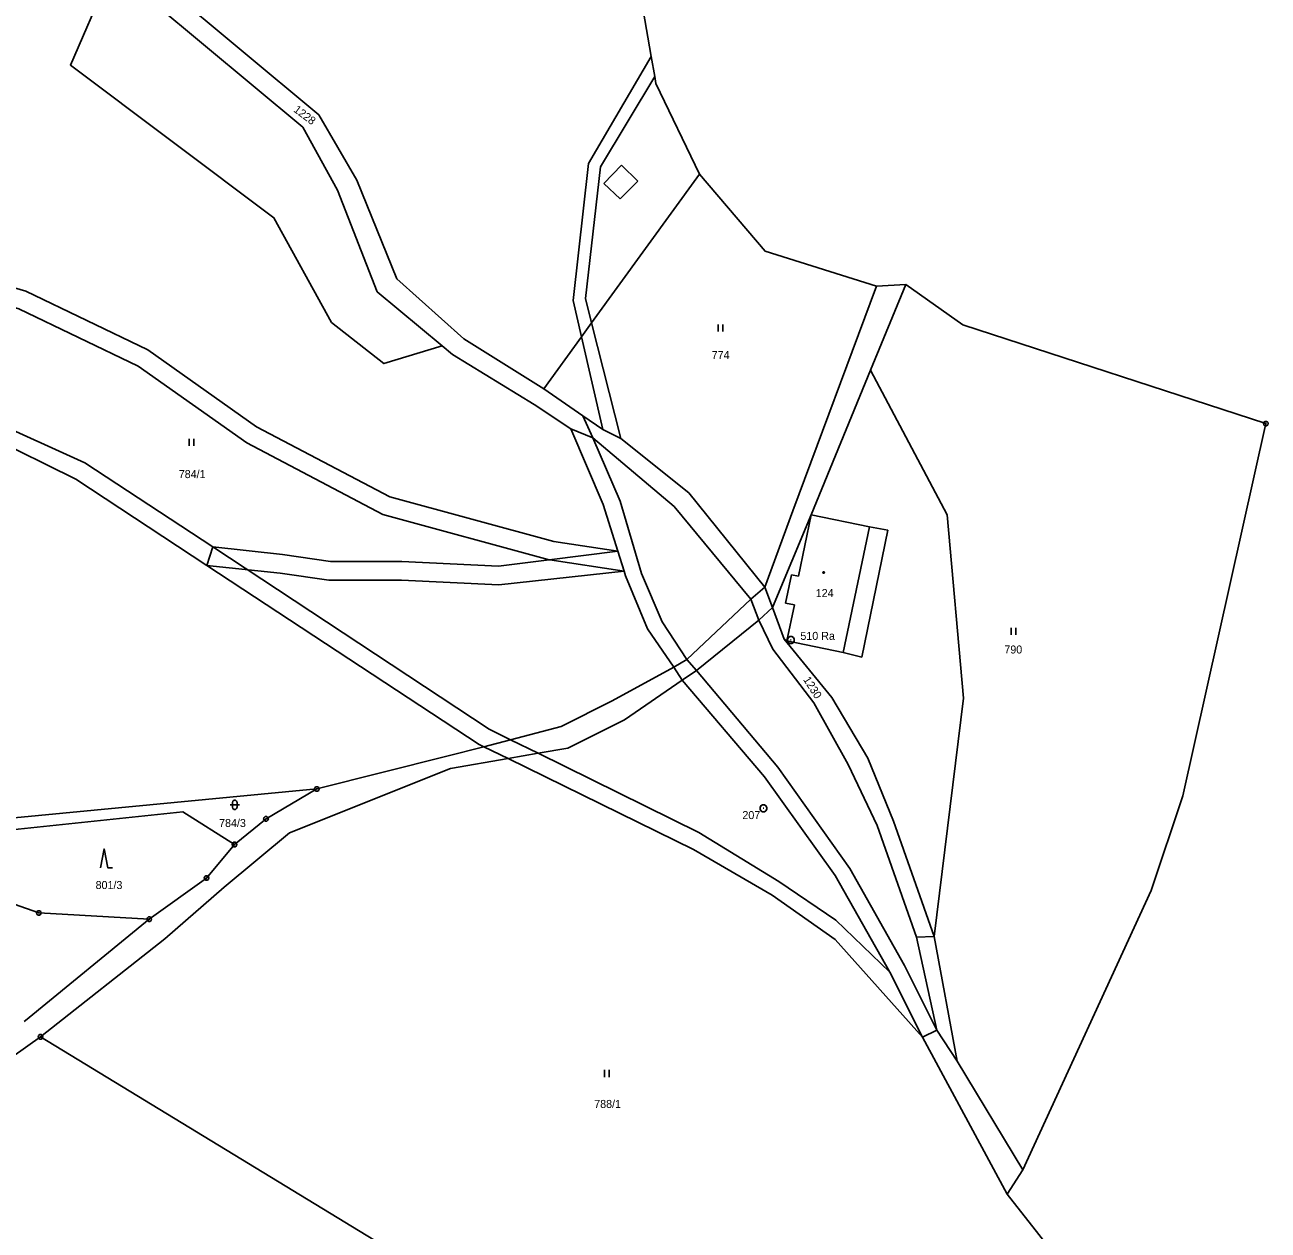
# Model space of a CAD drawing. Extents: x -694465 to -690527, y -983694 to -978978.
# Drawn here: x -690812.1 to -690548.1, y -980700.1 to -980444.1 of the extents above; entities that cross this region are included whole.
import ezdxf

# ---------------------------------------------------------------- set-up
doc = ezdxf.new("R2010")
doc.units = 0
for name, color, linetype in [('Vrstva 1', 7, 'Continuous'), ('Vrstva 17', 7, 'Continuous'), ('Vrstva 18', 7, 'Continuous'), ('Vrstva 19', 7, 'Continuous'), ('Vrstva 24', 7, 'Continuous'), ('Vrstva 25', 7, 'Continuous')]:
    doc.layers.add(name, color=color, linetype=linetype)

msp = doc.modelspace()

# ---------------------------------------------------------------- linework, layer by layer
at = {"layer": 'Vrstva 1'}
for p, q in [((-690773.441, -980558.909), (-690772.204, -980554.98)), ((-690653.34, -980567.82), (-690654.96, -980563.48)), ((-690669.49, -980581.23), (-690671.54, -980578.89)), ((-690672.48, -980583.27), (-690674.28, -980580.53))]:
    msp.add_line(p, q, dxfattribs=at)
for points in [[(-690701.02, -980380.8), (-690680.82, -980440.94), (-690679.09, -980450.83)], [(-690794.567, -980434.438), (-690802.438, -980452.633), (-690759.222, -980485.064), (-690746.959, -980507.269), (-690735.863, -980516.034), (-690723.466, -980512.258)], [(-690749.68, -980463.23), (-690782.63, -980435.66)], [(-690784.75, -980439.47), (-690753.07, -980465.83)], [(-690679.09, -980450.83), (-690692.37, -980473.56)], [(-690679.09, -980450.83), (-690678.34, -980455.07)], [(-690689.82, -980474.23), (-690678.34, -980455.07)], [(-690678.34, -980455.07), (-690678.09, -980456.51), (-690668.82, -980475.78)], [(-690753.07, -980465.83), (-690745.71, -980479.19)], [(-690741.6, -980477.07), (-690749.68, -980463.23)], [(-690692.37, -980473.56), (-690695.68, -980502.64)], [(-690693.03, -980502.19), (-690689.82, -980474.23)], [(-690691.73, -980507.35), (-690668.82, -980475.78)], [(-690689.14, -980477.76), (-690685.42, -980473.89)], [(-690685.42, -980473.89), (-690681.94, -980477.28)], [(-690668.82, -980475.78), (-690654.9, -980492.15), (-690631.22, -980499.57)], [(-690733.13, -980498.05), (-690741.6, -980477.07)], [(-690685.66, -980481), (-690689.14, -980477.76)], [(-690681.94, -980477.28), (-690685.66, -980481)], [(-690745.71, -980479.19), (-690737.25, -980500.8)], [(-690686.191, -980555.869), (-690699.761, -980553.812), (-690734.587, -980544.354), (-690762.898, -980529.445), (-690786.026, -980513.096), (-690811.934, -980500.644), (-690829.339, -980495.559)], [(-690700.76, -980557.694), (-690736.061, -980548.098), (-690764.994, -980532.863), (-690788.062, -980516.556), (-690813.374, -980504.39), (-690830.692, -980499.335)], [(-690718.89, -980510.77), (-690733.13, -980498.05)], [(-690631.22, -980499.57), (-690649.01, -980547.32)], [(-690632.475, -980517.457), (-690624.99, -980499.23)], [(-690631.22, -980499.57), (-690624.99, -980499.23)], [(-690624.99, -980499.23), (-690612.88, -980507.83), (-690548.55, -980528.77)], [(-690737.25, -980500.8), (-690723.466, -980512.258)], [(-690695.68, -980502.64), (-690693.9, -980510.34)], [(-690691.73, -980507.35), (-690693.03, -980502.19)], [(-690693.9, -980510.34), (-690691.73, -980507.35)], [(-690685.55, -980531.94), (-690691.73, -980507.35)], [(-690701.9, -980521.36), (-690693.9, -980510.34)], [(-690693.9, -980510.34), (-690689.36, -980530.06)], [(-690723.466, -980512.258), (-690721.25, -980514.1)], [(-690701.9, -980521.36), (-690718.89, -980510.77)], [(-690721.25, -980514.1), (-690703.94, -980524.69)], [(-690645.08, -980548.15), (-690632.475, -980517.457)], [(-690618.97, -980637.71), (-690612.754, -980587.115), (-690616.185, -980548.133), (-690632.475, -980517.457)], [(-690693.593, -980527.123), (-690701.9, -980521.36)], [(-690703.94, -980524.69), (-690696.16, -980529.9)], [(-690819.55, -980527.99), (-690799.34, -980537.1)], [(-690689.36, -980530.06), (-690693.593, -980527.123)], [(-690691.46, -980531.79), (-690693.593, -980527.123)], [(-690548.55, -980528.77), (-690566.19, -980607.83), (-690572.88, -980627.97), (-690600.12, -980687.24)], [(-690801.3, -980540.6), (-690819.67, -980531.51)], [(-690696.16, -980529.9), (-690691.46, -980531.79)], [(-690696.16, -980529.9), (-690689.31, -980545.97)], [(-690691.46, -980531.79), (-690674.2, -980546.39)], [(-690685.7, -980545.22), (-690691.46, -980531.79)], [(-690685.55, -980531.94), (-690689.36, -980530.06)], [(-690671.12, -980543.47), (-690685.55, -980531.94)], [(-690799.34, -980537.1), (-690772.204, -980554.98)], [(-690773.441, -980558.909), (-690801.3, -980540.6)], [(-690654.96, -980563.48), (-690671.12, -980543.47)], [(-690689.31, -980545.97), (-690686.191, -980555.869)], [(-690681.16, -980560.62), (-690685.7, -980545.22)], [(-690674.2, -980546.39), (-690657.95, -980566.09)], [(-690649.01, -980547.32), (-690654.96, -980563.48)], [(-690653.34, -980567.82), (-690645.08, -980548.15)], [(-690647.81, -980561.21), (-690645.08, -980548.15)], [(-690632.71, -980550.73), (-690645.08, -980548.15)], [(-690632.71, -980550.73), (-690638.28, -980577.41)], [(-690634.35, -980578.39), (-690628.81, -980551.38)], [(-690628.81, -980551.38), (-690632.71, -980550.73)], [(-690700.76, -980557.694), (-690711.518, -980559.042), (-690732.011, -980558.042), (-690747.229, -980558.042), (-690757.419, -980556.55), (-690772.204, -980554.98)], [(-690772.204, -980554.98), (-690713.47, -980593.68)], [(-690686.191, -980555.869), (-690700.76, -980557.694)], [(-690684.851, -980560.121), (-690700.587, -980557.732), (-690700.754, -980557.687)], [(-690686.191, -980555.869), (-690684.851, -980560.121)], [(-690684.851, -980560.121), (-690711.426, -980563.052), (-690732.109, -980562.042), (-690747.521, -980562.042), (-690757.919, -980560.52), (-690773.441, -980558.909)], [(-690715.59, -980596.93), (-690773.441, -980558.909)], [(-690684.851, -980560.121), (-690684.53, -980561.14)], [(-690676.73, -980570.91), (-690681.16, -980560.62)], [(-690684.53, -980561.14), (-690679.86, -980572.39)], [(-690654.96, -980563.48), (-690657.95, -980566.09)], [(-690650.56, -980566.9), (-690649.3, -980560.9)], [(-690649.3, -980560.9), (-690647.81, -980561.21)], [(-690657.95, -980566.09), (-690671.54, -980578.89)], [(-690657.95, -980566.09), (-690656.25, -980570.51)], [(-690656.25, -980570.51), (-690653.34, -980567.82)], [(-690650.86, -980574.57), (-690653.34, -980567.82)], [(-690648.65, -980567.3), (-690650.56, -980566.9)], [(-690650.24, -980574.91), (-690648.65, -980567.3)], [(-690671.54, -980578.89), (-690676.73, -980570.91)], [(-690669.49, -980581.23), (-690656.25, -980570.51)], [(-690656.25, -980570.51), (-690653.28, -980576.7)], [(-690679.86, -980572.39), (-690674.28, -980580.53)], [(-690653.28, -980576.7), (-690644.54, -980588.08)], [(-690640.69, -980586.92), (-690650.86, -980574.57)], [(-690650.86, -980574.57), (-690650.24, -980574.91)], [(-690650.24, -980574.91), (-690638.28, -980577.41)], [(-690671.54, -980578.89), (-690674.28, -980580.53)], [(-690638.28, -980577.41), (-690634.35, -980578.39)], [(-690674.28, -980580.53), (-690687.4, -980587.66)], [(-690672.48, -980583.27), (-690669.49, -980581.23)], [(-690669.49, -980581.23), (-690652.22, -980601.74)], [(-690684.73, -980591.69), (-690672.48, -980583.27)], [(-690655.04, -980603.79), (-690672.48, -980583.27)], [(-690633.08, -980599.8), (-690640.69, -980586.92)], [(-690687.4, -980587.66), (-690698.19, -980593.13)], [(-690644.54, -980588.08), (-690637.25, -980601.19)], [(-690696.8, -980597.71), (-690684.73, -980591.69)], [(-690713.47, -980593.68), (-690708.94, -980595.91)], [(-690698.19, -980593.13), (-690708.94, -980595.91)], [(-690714.66, -980597.39), (-690722.5, -980599.41)], [(-690715.59, -980596.93), (-690714.66, -980597.39)], [(-690708.94, -980595.91), (-690714.66, -980597.39)], [(-690714.66, -980597.39), (-690709.48, -980599.92)], [(-690708.94, -980595.91), (-690703.07, -980598.8)], [(-690703.07, -980598.8), (-690696.8, -980597.71)], [(-690722.5, -980599.41), (-690750.09, -980606.37)], [(-690721.73, -980602.06), (-690709.48, -980599.92)], [(-690709.48, -980599.92), (-690703.07, -980598.8)], [(-690709.48, -980599.92), (-690670.1, -980619.21)], [(-690703.07, -980598.8), (-690668.94, -980615.62)], [(-690627.64, -980613.22), (-690633.08, -980599.8)], [(-690755.88, -980615.66), (-690721.73, -980602.06)], [(-690652.22, -980601.74), (-690636.88, -980623.27)], [(-690637.25, -980601.19), (-690631.09, -980614.14)], [(-690640.01, -980624.75), (-690655.04, -980603.79)], [(-690750.09, -980606.37), (-690827.76, -980613.79)], [(-690760.89, -980612.72), (-690750.09, -980606.37)], [(-690825.71, -980616.21), (-690778.54, -980611.24)], [(-690778.54, -980611.24), (-690767.59, -980618.16)], [(-690767.59, -980618.16), (-690760.89, -980612.72)], [(-690618.97, -980637.71), (-690627.64, -980613.22)], [(-690769.77, -980627.25), (-690755.88, -980615.66)], [(-690668.94, -980615.62), (-690651.94, -980626.06)], [(-690631.09, -980614.14), (-690622.73, -980637.83)], [(-690767.59, -980618.16), (-690773.51, -980625.29)], [(-690670.1, -980619.21), (-690653.42, -980628.92)], [(-690636.88, -980623.27), (-690625.28, -980643.88)], [(-690831.18, -980624.94), (-690809.14, -980632.7)], [(-690773.51, -980625.29), (-690785.69, -980634.03)], [(-690651.94, -980626.06), (-690639.89, -980634.27)], [(-690628.42, -980645.28), (-690640.01, -980624.75)], [(-690782.38, -980638.22), (-690769.77, -980627.25)], [(-690653.42, -980628.92), (-690640.01, -980638.35)], [(-690785.69, -980634.03), (-690811.94, -980655.55)], [(-690809.14, -980632.7), (-690785.69, -980634.03)], [(-690639.89, -980634.27), (-690628.42, -980645.28)], [(-690808.78, -980659.03), (-690782.38, -980638.22)], [(-690640.01, -980638.35), (-690621.46, -980659.12)], [(-690618.97, -980637.71), (-690622.73, -980637.83)], [(-690622.73, -980637.83), (-690618.41, -980657.63)], [(-690614.08, -980664.16), (-690618.97, -980637.71)], [(-690628.42, -980645.28), (-690621.46, -980659.12)], [(-690625.28, -980643.88), (-690618.41, -980657.63)], [(-690811.94, -980655.55), (-690812.276, -980655.788)], [(-690618.41, -980657.63), (-690621.46, -980659.12)], [(-690618.41, -980657.63), (-690614.08, -980664.16)], [(-690852.18, -980689.8), (-690808.78, -980659.03)], [(-690711.03, -980718.55), (-690808.78, -980659.03)], [(-690621.46, -980659.12), (-690603.48, -980692.41)], [(-690600.12, -980687.24), (-690614.08, -980664.16)], [(-690600.12, -980687.24), (-690603.48, -980692.41)], [(-690603.48, -980692.41), (-690590.03, -980709.6), (-690600.54, -980748.19), (-690613.3, -980778.07)]]:
    msp.add_lwpolyline(points, dxfattribs=at)
at = {"layer": 'Vrstva 24'}
for points in [[(-690548.396, -980528.294), (-690548.146, -980528.476), (-690548.05, -980528.77), (-690548.146, -980529.064), (-690548.396, -980529.246), (-690548.704, -980529.246), (-690548.954, -980529.064), (-690549.05, -980528.77), (-690548.954, -980528.476), (-690548.704, -980528.294)], [(-690548.396, -980528.294), (-690548.146, -980528.476), (-690548.05, -980528.77), (-690548.146, -980529.064), (-690548.396, -980529.246), (-690548.704, -980529.246), (-690548.954, -980529.064), (-690549.05, -980528.77), (-690548.954, -980528.476), (-690548.704, -980528.294)], [(-690548.396, -980528.294), (-690548.146, -980528.476), (-690548.05, -980528.77), (-690548.146, -980529.064), (-690548.396, -980529.246), (-690548.704, -980529.246), (-690548.954, -980529.064), (-690549.05, -980528.77), (-690548.954, -980528.476), (-690548.704, -980528.294)], [(-690649.226, -980573.996), (-690648.89, -980574.19), (-690648.696, -980574.526), (-690648.696, -980574.914), (-690648.89, -980575.25), (-690649.226, -980575.444), (-690649.614, -980575.444), (-690649.95, -980575.25), (-690650.144, -980574.914), (-690650.144, -980574.526), (-690649.95, -980574.19), (-690649.614, -980573.996)], [(-690749.936, -980605.894), (-690749.686, -980606.076), (-690749.59, -980606.37), (-690749.686, -980606.664), (-690749.936, -980606.846), (-690750.244, -980606.846), (-690750.494, -980606.664), (-690750.59, -980606.37), (-690750.494, -980606.076), (-690750.244, -980605.894)], [(-690655.046, -980609.756), (-690654.71, -980609.95), (-690654.516, -980610.286), (-690654.516, -980610.674), (-690654.71, -980611.01), (-690655.046, -980611.204), (-690655.434, -980611.204), (-690655.77, -980611.01), (-690655.964, -980610.674), (-690655.964, -980610.286), (-690655.77, -980609.95), (-690655.434, -980609.756)], [(-690760.736, -980612.244), (-690760.486, -980612.426), (-690760.39, -980612.72), (-690760.486, -980613.014), (-690760.736, -980613.196), (-690761.044, -980613.196), (-690761.294, -980613.014), (-690761.39, -980612.72), (-690761.294, -980612.426), (-690761.044, -980612.244)], [(-690767.436, -980617.684), (-690767.186, -980617.866), (-690767.09, -980618.16), (-690767.186, -980618.454), (-690767.436, -980618.636), (-690767.744, -980618.636), (-690767.994, -980618.454), (-690768.09, -980618.16), (-690767.994, -980617.866), (-690767.744, -980617.684)], [(-690773.356, -980624.814), (-690773.106, -980624.996), (-690773.01, -980625.29), (-690773.106, -980625.584), (-690773.356, -980625.766), (-690773.664, -980625.766), (-690773.914, -980625.584), (-690774.01, -980625.29), (-690773.914, -980624.996), (-690773.664, -980624.814)], [(-690808.986, -980632.224), (-690808.736, -980632.406), (-690808.64, -980632.7), (-690808.736, -980632.994), (-690808.986, -980633.176), (-690809.294, -980633.176), (-690809.544, -980632.994), (-690809.64, -980632.7), (-690809.544, -980632.406), (-690809.294, -980632.224)], [(-690785.536, -980633.554), (-690785.286, -980633.736), (-690785.19, -980634.03), (-690785.286, -980634.324), (-690785.536, -980634.506), (-690785.844, -980634.506), (-690786.094, -980634.324), (-690786.19, -980634.03), (-690786.094, -980633.736), (-690785.844, -980633.554)], [(-690808.626, -980658.554), (-690808.376, -980658.736), (-690808.28, -980659.03), (-690808.376, -980659.324), (-690808.626, -980659.506), (-690808.934, -980659.506), (-690809.184, -980659.324), (-690809.28, -980659.03), (-690809.184, -980658.736), (-690808.934, -980658.554)]]:
    msp.add_lwpolyline(points, close=True, dxfattribs=at)
for points in [[(-690548.669, -980528.77), (-690548.43, -980528.77)], [(-690548.669, -980528.77), (-690548.43, -980528.77)], [(-690548.669, -980528.77), (-690548.43, -980528.77)], [(-690649.47, -980574.72), (-690649.37, -980574.72)], [(-690750.209, -980606.37), (-690749.97, -980606.37)], [(-690655.29, -980610.48), (-690655.19, -980610.48)], [(-690761.009, -980612.72), (-690760.77, -980612.72)], [(-690767.709, -980618.16), (-690767.47, -980618.16)], [(-690773.629, -980625.29), (-690773.39, -980625.29)], [(-690809.259, -980632.7), (-690809.02, -980632.7)], [(-690785.809, -980634.03), (-690785.57, -980634.03)], [(-690808.899, -980659.03), (-690808.66, -980659.03)]]:
    msp.add_lwpolyline(points, dxfattribs=at)
at = {"layer": 'Vrstva 25'}
for points in [[(-690664.87, -980507.73), (-690664.87, -980509.23)], [(-690663.87, -980509.23), (-690663.87, -980507.73)], [(-690777.19, -980532.03), (-690777.19, -980533.53)], [(-690776.19, -980533.53), (-690776.19, -980532.03)], [(-690602.63, -980572.16), (-690602.63, -980573.66)], [(-690601.63, -980573.66), (-690601.63, -980572.16)], [(-690768.53, -980609.76), (-690766.53, -980609.76)], [(-690796.02, -980623.09), (-690795.27, -980619.09), (-690794.52, -980623.09), (-690793.52, -980623.09)], [(-690689, -980666.05), (-690689, -980667.55)], [(-690688, -980667.55), (-690688, -980666.05)]]:
    msp.add_lwpolyline(points, dxfattribs=at)
for points in [[(-690642.373, -980560.258), (-690642.285, -980560.41), (-690642.373, -980560.562), (-690642.547, -980560.562), (-690642.635, -980560.41), (-690642.547, -980560.258)], [(-690768.03, -980609.26), (-690767.935, -980608.966), (-690767.685, -980608.784), (-690767.375, -980608.784), (-690767.125, -980608.966), (-690767.03, -980609.26), (-690767.03, -980610.26), (-690767.125, -980610.554), (-690767.375, -980610.736), (-690767.685, -980610.736), (-690767.935, -980610.554), (-690768.03, -980610.26)]]:
    msp.add_lwpolyline(points, close=True, dxfattribs=at)

# ---------------------------------------------------------------- texts
at = {"layer": 'Vrstva 17'}
for s, p in [('510 Ra', (-690647.393, -980574.71)), ('207', (-690659.713, -980612.77))]:
    msp.add_text(s, height=1.7, dxfattribs=at).set_placement(p)
at = {"layer": 'Vrstva 18'}
for s, rotation, p in [('1228', 323.0909, (-690755.189, -980462.391)), ('1230', 302.40713, (-690646.871, -980583.134))]:
    msp.add_text(s, height=1.7, rotation=rotation, dxfattribs=at).set_placement(p)
for s, p in [('774', (-690666.234, -980515.05)), ('784/1', (-690779.423, -980540.35)), ('790', (-690604.071, -980577.6)), ('784/3', (-690770.857, -980614.45)), ('801/3', (-690797.083, -980627.63)), ('788/1', (-690691.183, -980674.12))]:
    msp.add_text(s, height=1.7, dxfattribs=at).set_placement(p)
at = {"layer": 'Vrstva 19'}
msp.add_text('124', height=1.7, dxfattribs=at).set_placement((-690644.14, -980565.61))

doc.saveas('drawing.dxf')
